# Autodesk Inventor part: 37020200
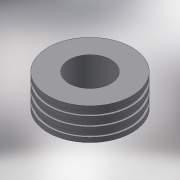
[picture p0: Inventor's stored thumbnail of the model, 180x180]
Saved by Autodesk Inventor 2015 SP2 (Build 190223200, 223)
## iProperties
Created: 2017-08
Part Number: 37020200
Material: Generic
Description: PLASSON MAN HOLE ADAPTOR 200
Document SubType Name: Modeling
Designer: Кирилл
Density: 1 g/cm^3
Appearance: Default
Author: Кирилл
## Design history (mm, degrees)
derived "37020-477207.ipt"
feature "Solid1::37020-477207.ipt"
tag "TaggingFeature1"
body "Solid1"
other parameters: "d0" = 135, "d1" = 355, "d2" = 337.25, "d3" = 176, "d6" = 56, "L_" = 135, "d_1" = 176, "D_" = 355, "H_" = 56
